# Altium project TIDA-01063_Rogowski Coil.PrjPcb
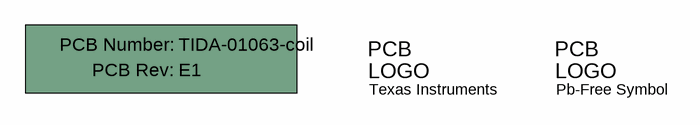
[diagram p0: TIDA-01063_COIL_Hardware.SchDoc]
CopyrightYear: 2016; EVM_Orderable: N/A; PCB_Layout: Avinash N; PCB_Rev: E1; PRJ_Customer: Public Release; PRJ_Engineer: Srinivasan Iyer; PRJ_Number: TIDA-01063-coil; PRJ_Title: Rogowski Coil; SCH_Rev: E1; TechSupport: http://www.ti.com/support; TID: TIDA-01063_Coil
1 sheet, 3 parts. Net scope: global (net labels, ports and power ports of the same name join across sheets).
Board file: TIDA-01063_COIL.PcbDoc

## Sheet TIDA-01063_COIL_Hardware.SchDoc: Rogowski Coil PCB Hardware
size 431 x 279 mm; Date: Not shown in title block; ApprovedBy: Not shown in title block; CheckedBy: Not shown in title block; Author: Not shown in title block; CompanyName: Not shown in title block; Engineer: Not shown in title block; Organization: Not shown in title block; Address1: Not shown in title block; Address2: Not shown in title block; Address3: Not shown in title block; Address4: Not shown in title block; DocumentNumber: 1; Revision: Use project parameter SCH_Rev; SheetNumber: 3; SheetTotal: 3; PageSetup: Record=PageOptions¦CenterHorizontal=True¦CenterVertical=True¦PrintScale=1.00¦XCorrection=1.00¦YCorrection=1.00¦PrintKind=0¦BorderSize=5000000¦LeftOffset=0¦BottomOffset=0¦Orientation=2¦PaperLength=1000¦PaperWidth=1000¦Scale=100¦PaperSource=15¦PrintQuality=600¦MediaType=1¦DitherType=10¦PaperKind=Letter¦PrintScaleMode=1

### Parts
!PCB  Printed Circuit Board  (value not drawn)  (mechanical)
Logo1  Texas Instruments  [TI_Stacked_Overlay_Small]  (no BOM)
Logo2  Pb-Free Symbol  [Pb-Free_Overlay_Small]  (no BOM)

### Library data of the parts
!PCB = PCB: Manufacturer: Any; PartNumber: TIDA-01063-coil; SymbolCreator: a0412235
Logo1 = TI_Logo: Texas Instrument Corporate Signature; SymbolCreator: codlsc
Logo2 = Pb-Free: SymbolCreator: a0412235

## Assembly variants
001: not fitted FID1 FID2 FID3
